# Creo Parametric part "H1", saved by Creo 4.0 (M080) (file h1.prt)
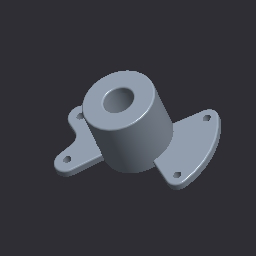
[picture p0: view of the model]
Units: Inch lbm Second (Pro/E Default); INCH, POUND, SECS

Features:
  1. datum plane "DTM1"
  2. datum plane "DTM2"
  3. datum plane "DTM3"
  4. protrusion
  5. protrusion
  6. protrusion
  7. round
  8. hole
  9. round
  10. hole
  11. hole
  12. hole
  13. hole
  14. cut

Layers: BASE_DAT, BLANK

Surfaces: 20 cylinder, 11 plane, 10 torus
